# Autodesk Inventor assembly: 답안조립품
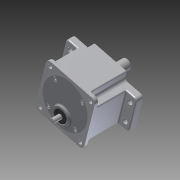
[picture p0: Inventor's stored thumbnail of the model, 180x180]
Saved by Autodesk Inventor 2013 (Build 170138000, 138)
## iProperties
Created: 2015-07
Part Number: 답안조립품
Document SubType Name: Assembly
Designer: user
Author: user
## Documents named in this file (12)
- C:\Users\user\Desktop\450734V1026\답안조립품.iam
- C:\Users\user\Desktop\450734V1026\메인축.ipt
- C:\Users\user\Desktop\450734V1026\서브축.ipt
- C:\Users\user\Desktop\450734V1026\베어링 608.ipt
- 베어링 608.ipt
- C:\Users\user\Desktop\450734V1026\베어링 6003.ipt
- 베어링 6003.ipt
- C:\Users\user\Desktop\450734V1026\본체.ipt
- C:\Users\user\Desktop\450734V1026\커버.ipt
- C:\Users\user\Desktop\450734V1026\M4x0.5x16.ipt
- C:\Users\user\Desktop\450734V1026\오일실 8x22x7.ipt
- C:\Users\user\Desktop\450734V1026\오일실 17x32x8.ipt
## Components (4 placed, 1 different names)
1. M4x0.5x12:1
2. M4x0.5x12:2
3. M4x0.5x12:3
4. M4x0.5x12:4
